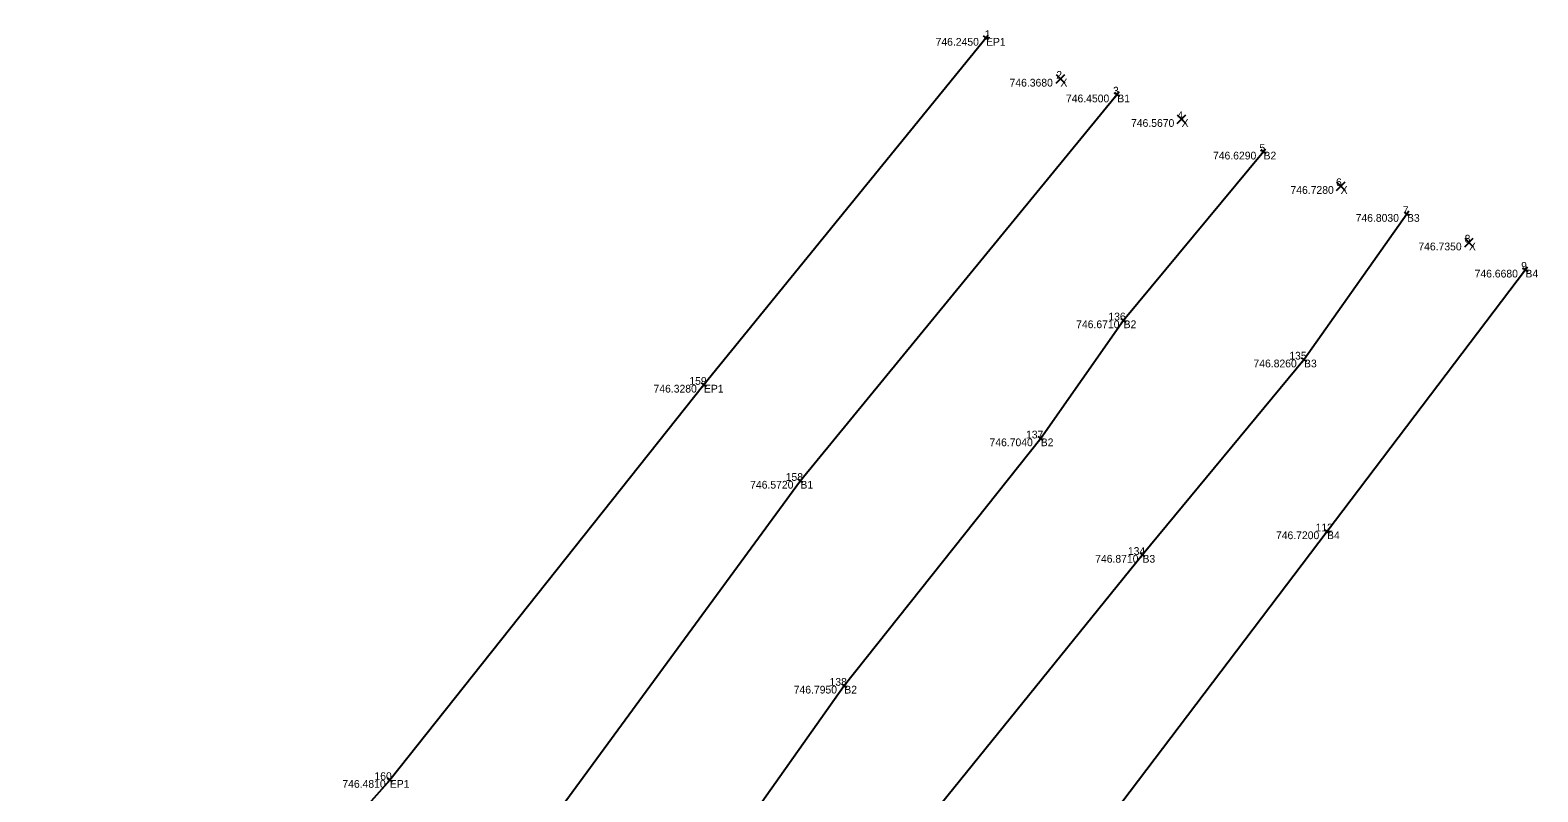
# Model space of a CAD drawing. Extents: x 1857337 to 1857837, y 693958 to 694371.
# Drawn here: x 1857604.7 to 1857721.3, y 694312.5 to 694371.4 of the extents above; entities that cross this region are included whole.
import ezdxf

# ---------------------------------------------------------------- set-up
doc = ezdxf.new("R2010")
doc.units = 0
for name, color, linetype in [('BR_X_SV_Pier_Cap_Bottom', 7, 'Continuous'), ('SV_X_Random_Point', 7, 'Continuous'), ('SV_X_Text_Comment', 7, 'Continuous'), ('SV_X_Text_Description', 7, 'Continuous'), ('SV_X_Text_Elevation', 7, 'Continuous'), ('SV_X_Text_Name', 7, 'Continuous'), ('UT_X_Electric_Cells', 7, 'Continuous')]:
    doc.layers.add(name, color=color, linetype=linetype)

msp = doc.modelspace()

# ---------------------------------------------------------------- linework, layer by layer
at = {"layer": 'BR_X_SV_Pier_Cap_Bottom'}
for p, q in [((1857678.81, 694370.69), (1857678.42, 694371)), ((1857678.77, 694371.04), (1857678.45, 694370.65)), ((1857678.61, 694370.84), (1857678.61, 694370.84)), ((1857688.95, 694366.31), (1857688.56, 694366.62)), ((1857688.91, 694366.66), (1857688.6, 694366.27)), ((1857688.76, 694366.46), (1857688.76, 694366.46)), ((1857700.23, 694362.23), (1857699.91, 694361.85)), ((1857700.27, 694361.88), (1857699.88, 694362.2)), ((1857700.07, 694362.04), (1857700.07, 694362.04)), ((1857711.36, 694357.08), (1857710.96, 694357.37)), ((1857711.3, 694357.43), (1857711.02, 694357.02)), ((1857711.16, 694357.22), (1857711.16, 694357.22)), ((1857720.52, 694352.76), (1857720.12, 694353.06)), ((1857720.47, 694353.11), (1857720.17, 694352.71)), ((1857720.32, 694352.91), (1857720.32, 694352.91)), ((1857689.44, 694348.83), (1857689.05, 694349.15)), ((1857689.41, 694349.19), (1857689.09, 694348.8)), ((1857689.25, 694348.99), (1857689.25, 694348.99)), ((1857703.41, 694345.81), (1857703, 694346.1)), ((1857703.35, 694346.16), (1857703.06, 694345.75)), ((1857703.2, 694345.96), (1857703.2, 694345.96)), ((1857657, 694343.86), (1857656.61, 694344.17)), ((1857656.96, 694344.21), (1857656.65, 694343.82)), ((1857656.8, 694344.01), (1857656.8, 694344.01)), ((1857683.04, 694339.71), (1857682.63, 694340)), ((1857682.98, 694340.06), (1857682.69, 694339.65)), ((1857682.84, 694339.86), (1857682.84, 694339.86)), ((1857664.45, 694336.42), (1857664.06, 694336.73)), ((1857664.41, 694336.77), (1857664.1, 694336.38)), ((1857664.26, 694336.58), (1857664.26, 694336.58)), ((1857705.17, 694332.52), (1857704.78, 694332.82)), ((1857705.13, 694332.87), (1857704.82, 694332.47)), ((1857704.98, 694332.67), (1857704.98, 694332.67)), ((1857690.9, 694330.69), (1857690.52, 694331)), ((1857690.87, 694331.04), (1857690.55, 694330.65)), ((1857690.71, 694330.85), (1857690.71, 694330.85)), ((1857667.85, 694320.57), (1857667.45, 694320.88)), ((1857667.81, 694320.92), (1857667.49, 694320.53)), ((1857667.65, 694320.73), (1857667.65, 694320.73)), ((1857632.71, 694313.29), (1857632.32, 694313.6)), ((1857632.67, 694313.64), (1857632.36, 694313.25)), ((1857632.51, 694313.44), (1857632.51, 694313.44))]:
    msp.add_line(p, q, dxfattribs=at)
at = {"layer": 'SV_X_Random_Point'}
msp.add_lwpolyline([(1857678.61, 694370.84), (1857656.8, 694344.01), (1857632.51, 694313.44), (1857612.98, 694291.43), (1857598.98, 694274.19), (1857584.32, 694256.28)], dxfattribs=at)
at = {"layer": 'SV_X_Text_Elevation'}
for p, q in [((1857684.03, 694367.35), (1857684.69, 694368.01)), ((1857684.03, 694368.01), (1857684.69, 694367.35)), ((1857693.39, 694364.22), (1857694.06, 694364.89)), ((1857693.39, 694364.89), (1857694.06, 694364.22)), ((1857705.7, 694359.04), (1857706.37, 694359.71)), ((1857705.7, 694359.71), (1857706.37, 694359.04)), ((1857715.62, 694354.67), (1857716.28, 694355.34)), ((1857715.62, 694355.34), (1857716.28, 694354.67))]:
    msp.add_line(p, q, dxfattribs=at)
at = {"layer": 'UT_X_Electric_Cells'}
for points in [[(1857688.76, 694366.46), (1857664.26, 694336.58), (1857640.4, 694304), (1857624.29, 694283.66), (1857611.11, 694265.29), (1857596.56, 694246.69), (1857577.55, 694221.21), (1857552.76, 694187.23), (1857529.48, 694157.73), (1857506.44, 694129.2)], [(1857700.07, 694362.04), (1857689.25, 694348.99), (1857682.84, 694339.86), (1857667.65, 694320.73), (1857658.45, 694307.7), (1857647.3, 694293.67), (1857639.92, 694285.28), (1857631.25, 694272.58), (1857620.54, 694259.56), (1857609.95, 694246.13), (1857585.77, 694213.92), (1857569.94, 694193.46), (1857560.42, 694180.39), (1857538.66, 694151.42), (1857515.13, 694123.12)], [(1857711.16, 694357.22), (1857703.2, 694345.96), (1857690.71, 694330.85), (1857675.14, 694311.61), (1857665.25, 694297.05), (1857650.19, 694279.11), (1857639.82, 694265.06), (1857626.46, 694247.57), (1857616.28, 694234.21), (1857602.42, 694215.52), (1857593.56, 694204.62), (1857579.14, 694185.2), (1857570.86, 694174.07), (1857548.44, 694145.75), (1857525.39, 694115.5)], [(1857720.32, 694352.91), (1857704.98, 694332.67), (1857684.03, 694304.99), (1857662.01, 694274.86), (1857649.39, 694258.92), (1857636.49, 694241.06), (1857621.4, 694221.62), (1857600.9, 694194.58), (1857569.51, 694153.93), (1857555.9, 694136.99), (1857538.65, 694113.77)]]:
    msp.add_lwpolyline(points, dxfattribs=at)

# ---------------------------------------------------------------- texts
at = {"layer": 'SV_X_Text_Comment'}
for s, p in [('EP1', (1857678.61, 694370.24)), ('X', (1857684.36, 694367.08)), ('B1', (1857688.76, 694365.86)), ('X', (1857693.73, 694363.96)), ('B2', (1857700.07, 694361.44)), ('X', (1857706.03, 694358.78)), ('B3', (1857711.16, 694356.62)), ('X', (1857715.95, 694354.41)), ('B4', (1857720.32, 694352.31)), ('B2', (1857689.25, 694348.39)), ('B3', (1857703.2, 694345.36)), ('EP1', (1857656.8, 694343.41)), ('B2', (1857682.84, 694339.26)), ('B1', (1857664.26, 694335.98)), ('B4', (1857704.98, 694332.07)), ('B3', (1857690.71, 694330.25)), ('B2', (1857667.65, 694320.13)), ('EP1', (1857632.51, 694312.84))]:
    msp.add_text(s, height=0.6, dxfattribs=at).set_placement(p)
at = {"layer": 'SV_X_Text_Description'}
for s, p in [('746.2450', (1857674.71, 694370.24)), ('746.3680', (1857680.43, 694367.08)), ('746.4500', (1857684.79, 694365.86)), ('746.5670', (1857689.82, 694363.96)), ('746.6290', (1857696.16, 694361.44)), ('746.7280', (1857702.15, 694358.78)), ('746.8030', (1857707.19, 694356.62)), ('746.7350', (1857712.04, 694354.41)), ('746.6680', (1857716.39, 694352.31)), ('746.6710', (1857685.58, 694348.39)), ('746.8260', (1857699.29, 694345.36)), ('746.3280', (1857652.9, 694343.41)), ('746.7040', (1857678.88, 694339.26)), ('746.5720', (1857660.37, 694335.98)), ('746.7200', (1857701.03, 694332.07)), ('746.8710', (1857687.05, 694330.25)), ('746.7950', (1857663.74, 694320.13)), ('746.4810', (1857628.84, 694312.84))]:
    msp.add_text(s, height=0.6, dxfattribs=at).set_placement(p)
at = {"layer": 'SV_X_Text_Name'}
for s, p in [('1', (1857678.51, 694370.84)), ('2', (1857684.04, 694367.68)), ('3', (1857688.43, 694366.46)), ('4', (1857693.4, 694364.56)), ('5', (1857699.75, 694362.04)), ('6', (1857705.67, 694359.38)), ('7', (1857710.83, 694357.22)), ('8', (1857715.62, 694355.01)), ('9', (1857719.99, 694352.91)), ('136', (1857688.07, 694348.99)), ('135', (1857702.06, 694345.96)), ('159', (1857655.67, 694344.01)), ('137', (1857681.7, 694339.86)), ('158', (1857663.12, 694336.58)), ('112', (1857704.09, 694332.67)), ('134', (1857689.58, 694330.85)), ('138', (1857666.51, 694320.73)), ('160', (1857631.32, 694313.44))]:
    msp.add_text(s, height=0.6, dxfattribs=at).set_placement(p)

doc.saveas('drawing.dxf')
